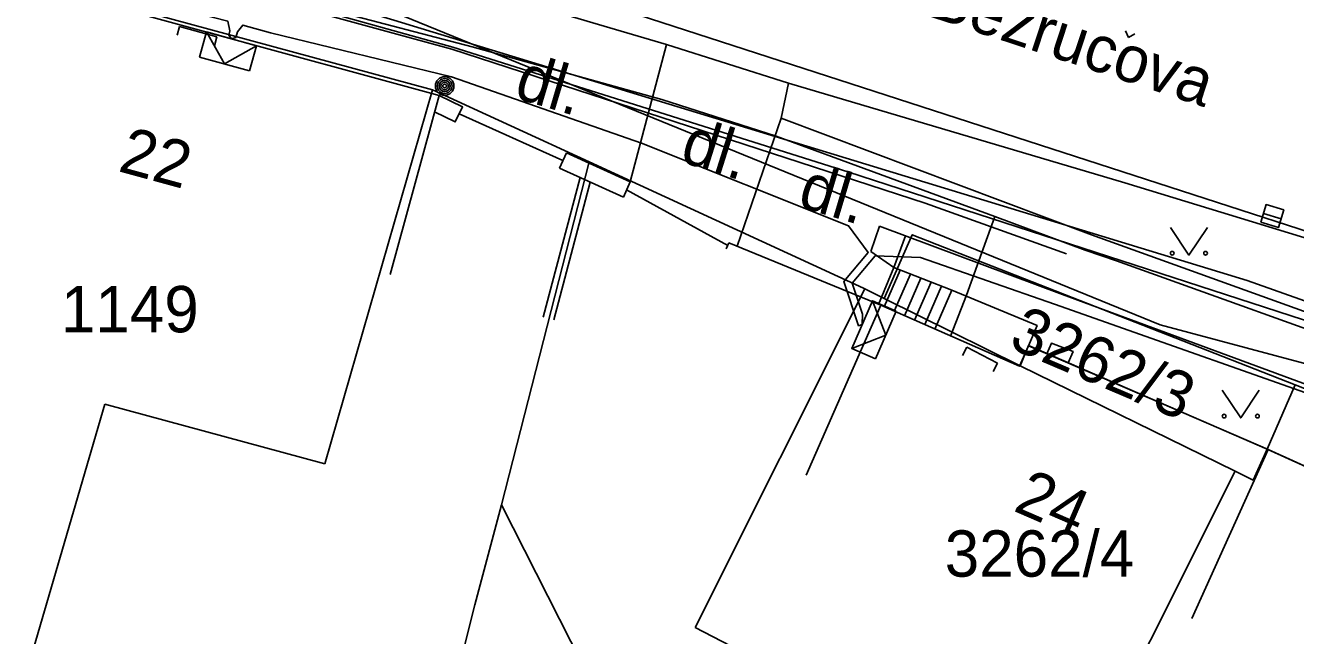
# Model space of a CAD drawing. Extents: x -601580 to 4, y -1204314 to 4.
# Drawn here: x -599783.34 to -599749.08, y -1203349.28 to -1203332.82 of the extents above; entities that cross this region are included whole.
import ezdxf

# ---------------------------------------------------------------- set-up
doc = ezdxf.new("R2010")
doc.units = 0
for name, color, linetype in [('00-EON NN', 7, 'Continuous'), ('00-INNOGY-NTL', 7, 'Continuous'), ('00-KN-HRANICE PARCEL', 7, 'Continuous'), ('00-KN-PARC. CISLA', 7, 'Continuous'), ('00-KN-VNITRNI KRESBA', 7, 'Continuous'), ('00-POLOHOPIS', 7, 'Continuous'), ('00-SITE KOM. KABEL', 7, 'Continuous'), ('00-VAK-VODA-RAD IGIS', 7, 'Continuous'), ('Vrstva 25', 7, 'Continuous'), ('Vrstva 26', 7, 'Continuous'), ('Vrstva 27', 7, 'Continuous'), ('Vrstva 36', 7, 'Continuous'), ('Vrstva 6', 7, 'Continuous'), ('Vrstva 9', 7, 'Continuous')]:
    doc.layers.add(name, color=color, linetype=linetype)

# ---------------------------------------------------------------- blocks, each defined once
blk = doc.blocks.new('6.01A_1266')
at = {"layer": 'Vrstva 25'}
for radius in [0.25, 0.2, 0.15, 0.1, 0.05]:
    blk.add_circle((0, 0), radius, dxfattribs=at)
blk = doc.blocks.new('6.30_324')
at = {"layer": 'Vrstva 27'}
blk.add_line((-0.25, 0), (0.25, 0), dxfattribs=at)
blk.add_lwpolyline([(-0.25, -0.25), (0.25, -0.25), (0.25, 0.25), (-0.25, 0.25)], close=True, dxfattribs=at)
blk = doc.blocks.new('3.14_144')
at = {"layer": 'Vrstva 36'}
blk.add_lwpolyline([(-0.5, 0.75), (0, 0), (0.5, 0.75)], dxfattribs=at)
for centre in [(-0.45, 0.05), (0.449, 0.05)]:
    blk.add_circle(centre, 0.05, dxfattribs=at)
blk = doc.blocks.new('3.14_154')
at = {"layer": 'Vrstva 36'}
blk.add_lwpolyline([(-0.5, 0.75), (0, 0), (0.5, 0.75)], dxfattribs=at)
for centre in [(-0.45, 0.05), (0.449, 0.05)]:
    blk.add_circle(centre, 0.05, dxfattribs=at)
blk = doc.blocks.new('VCHOD_252')
at = {"layer": 'Vrstva 6'}
blk.add_line((0, 0.25), (0, 0), dxfattribs=at)
blk = doc.blocks.new('VCHOD_254')
at = {"layer": 'Vrstva 6'}
blk.add_line((0, 0.25), (0, 0), dxfattribs=at)
blk = doc.blocks.new('VCHOD_256')
at = {"layer": 'Vrstva 6'}
blk.add_line((0, 0.25), (0, 0), dxfattribs=at)
blk = doc.blocks.new('VCHOD_258')
at = {"layer": 'Vrstva 6'}
blk.add_line((0, 0.25), (0, 0), dxfattribs=at)
blk = doc.blocks.new('NN630')
at = {"layer": 'Vrstva 9'}
for points in [[(-3, -700), (-703, 0)], [(-703, -700), (-703, 0), (697, 0), (697, -700)], [(-3, -700), (697, 0)], [(-703, -700), (697, -700)]]:
    blk.add_lwpolyline(points, dxfattribs=at)

msp = doc.modelspace()

# ---------------------------------------------------------------- linework, layer by layer
at = {"layer": '00-EON NN'}
for points in [[(-599786.53, -1203330.36), (-599782.77, -1203331.45), (-599777.88, -1203332.71), (-599777.827, -1203332.968), (-599777.86, -1203333.086), (-599777.783, -1203333.184), (-599777.669, -1203333.146), (-599777.626, -1203332.99), (-599777.48, -1203332.81), (-599776.73, -1203333.02), (-599771.85, -1203334.21), (-599766.72, -1203336), (-599761.14, -1203338.23), (-599760.611, -1203338.947), (-599761.262, -1203339.729), (-599760.866, -1203340.921), (-599760.771, -1203340.889)], [(-599760.771, -1203340.889), (-599760.759, -1203340.609), (-599761.038, -1203339.771), (-599760.423, -1203339.035), (-599759.2, -1203339.08), (-599755.58, -1203340.34), (-599747.12, -1203343.33), (-599742.31, -1203345.18), (-599739.75, -1203346.25), (-599739.539, -1203346.483), (-599739.944, -1203347.797), (-599740.403, -1203348.953), (-599740.344, -1203349.075), (-599740.222, -1203349.039), (-599739.756, -1203347.863), (-599739.289, -1203346.359), (-599739.12, -1203346.15), (-599735.04, -1203347.7), (-599731.04, -1203349.25), (-599729.807, -1203349.645)]]:
    msp.add_lwpolyline(points, dxfattribs=at)
at = {"layer": '00-INNOGY-NTL'}
msp.add_lwpolyline([(-599755.262, -1203338.986), (-599759.07, -1203337.62), (-599771.84, -1203333.46), (-599779.26, -1203331.43), (-599784.38, -1203330.03), (-599784.72, -1203329.94), (-599809.28, -1203323.19), (-599809.78, -1203323.05), (-599823.19, -1203319.4)], dxfattribs=at)
at = {"layer": '00-KN-HRANICE PARCEL'}
for p, q in [((-599770.5, -1203345.75), (-599768.14, -1203336.5)), ((-599760.74, -1203339.91), (-599768.14, -1203336.5)), ((-599756.51, -1203342), (-599760.18, -1203340.19)), ((-599750.71, -1203344.85), (-599756.51, -1203342)), ((-599749.85, -1203344.25), (-599749.09, -1203342.52)), ((-599749.09, -1203342.52), (-599731.4, -1203349.49)), ((-599771.22, -1203348.45), (-599770.5, -1203345.75)), ((-599762.11, -1203362.29), (-599770.5, -1203345.75)), ((-599773.46, -1203357.4), (-599771.22, -1203348.45))]:
    msp.add_line(p, q, dxfattribs=at)
for points in [[(-599921.72, -1203290.33), (-599917.89, -1203290.73), (-599893.03, -1203296.87), (-599826.78, -1203316.44), (-599809.21, -1203321.87), (-599773.41, -1203332.68), (-599750.39, -1203339.7), (-599709.77, -1203354.1), (-599677.07, -1203366.64), (-599676.9, -1203368.84), (-599676.98, -1203369.55)], [(-599768.14, -1203336.5), (-599772.36, -1203334.56), (-599784.87, -1203331.16)], [(-599760.18, -1203340.19), (-599759.42, -1203338.47), (-599749.09, -1203342.52)], [(-599760.18, -1203340.19), (-599760.7, -1203339.93), (-599760.74, -1203339.91)], [(-599756.51, -1203342), (-599756.28, -1203341.46), (-599749.85, -1203344.25)], [(-599749.85, -1203344.25), (-599750.22, -1203345.09), (-599750.71, -1203344.85)], [(-599740.06, -1203349.19), (-599743.74, -1203347.58), (-599743.53, -1203347.11), (-599749.85, -1203344.25)], [(-599750.71, -1203344.85), (-599755.29, -1203353.98), (-599755.39, -1203354.18), (-599759.18, -1203361.73)]]:
    msp.add_lwpolyline(points, dxfattribs=at)
at = {"layer": '00-KN-VNITRNI KRESBA'}
for p, q in [((-599772.36, -1203334.56), (-599775.27, -1203344.65)), ((-599765.28, -1203349.06), (-599760.7, -1203339.93)), ((-599781.2, -1203343.04), (-599783.98, -1203352.56)), ((-599775.27, -1203344.65), (-599781.2, -1203343.04)), ((-599755.39, -1203354.18), (-599765.28, -1203349.06))]:
    msp.add_line(p, q, dxfattribs=at)
at = {"layer": '00-POLOHOPIS'}
for p, q in [((-599771.919, -1203331.604), (-599766.046, -1203333.336)), ((-599778.178, -1203333.13), (-599779.184, -1203332.846)), ((-599766.046, -1203333.336), (-599767.027, -1203337.043)), ((-599766.046, -1203333.336), (-599762.755, -1203334.376)), ((-599762.953, -1203335.326), (-599762.755, -1203334.376)), ((-599762.755, -1203334.376), (-599753.685, -1203337.067)), ((-599768.844, -1203336.468), (-599771.646, -1203335.21)), ((-599762.953, -1203335.326), (-599764.14, -1203338.778)), ((-599754.589, -1203338.472), (-599762.953, -1203335.326)), ((-599768.75, -1203336.261), (-599768.936, -1203336.671)), ((-599767.027, -1203337.043), (-599768.75, -1203336.261)), ((-599768.936, -1203336.671), (-599767.213, -1203337.453)), ((-599768.382, -1203336.922), (-599769.375, -1203340.69)), ((-599768.105, -1203337.048), (-599769.085, -1203340.767)), ((-599767.213, -1203337.453), (-599767.027, -1203337.043)), ((-599753.685, -1203337.067), (-599747.822, -1203338.86)), ((-599764.398, -1203338.759), (-599767.126, -1203337.26)), ((-599760.536, -1203338.924), (-599760.304, -1203338.237)), ((-599760.304, -1203338.237), (-599755.364, -1203340.081)), ((-599759.603, -1203338.499), (-599759.921, -1203339.351)), ((-599748.418, -1203340.694), (-599754.589, -1203338.472)), ((-599764.367, -1203338.684), (-599764.436, -1203338.85)), ((-599764.367, -1203338.684), (-599760.271, -1203340.371)), ((-599759.921, -1203339.351), (-599760.536, -1203338.924)), ((-599760.182, -1203340.41), (-599759.748, -1203339.419)), ((-599759.907, -1203340.53), (-599759.468, -1203339.529)), ((-599759.632, -1203340.651), (-599759.188, -1203339.638)), ((-599759.357, -1203340.771), (-599758.909, -1203339.748)), ((-599759.083, -1203340.892), (-599758.629, -1203339.857)), ((-599758.808, -1203341.012), (-599758.35, -1203339.967)), ((-599755.364, -1203340.081), (-599742.153, -1203344.961)), ((-599757.952, -1203341.502), (-599757.124, -1203341.931))]:
    msp.add_line(p, q, dxfattribs=at)
for points in [[(-599773.501, -1203339.536), (-599772.184, -1203334.712), (-599784.724, -1203331.289), (-599786.041, -1203336.112)], [(-599753.668, -1203332.964), (-599753.59, -1203333.148)], [(-599753.416, -1203333.049), (-599753.59, -1203333.148)], [(-599772.184, -1203334.712), (-599771.553, -1203335.02), (-599771.75, -1203335.424), (-599772.305, -1203335.154)], [(-599756.284, -1203341.463), (-599756.052, -1203340.919), (-599758.35, -1203339.967), (-599759.921, -1203339.351), (-599760.331, -1203340.346)], [(-599751.882, -1203348.82), (-599749.819, -1203344.265), (-599756.284, -1203341.463), (-599756.523, -1203342.014), (-599760.271, -1203340.371), (-599762.278, -1203344.951)], [(-599755.215, -1203341.926), (-599755.082, -1203341.619), (-599755.665, -1203341.393), (-599755.788, -1203341.678)], [(-599742.03, -1203353.8), (-599739.968, -1203349.245), (-599743.729, -1203347.542), (-599743.534, -1203347.111), (-599749.819, -1203344.265), (-599751.882, -1203348.82)]]:
    msp.add_lwpolyline(points, dxfattribs=at)
at = {"layer": '00-SITE KOM. KABEL'}
for points in [[(-599790.07, -1203328.52), (-599779.22, -1203331.34), (-599771.81, -1203333.41), (-599761.16, -1203336.77), (-599748.51, -1203340.88), (-599738.08, -1203344.54)], [(-599757.19, -1203337.98), (-599763.09, -1203335.81), (-599766.18, -1203334.82), (-599771.29, -1203333.4), (-599778.72, -1203331.45)], [(-599771.29, -1203333.4), (-599766.18, -1203334.82), (-599763.09, -1203335.81)], [(-599758.39, -1203341.2), (-599757.96, -1203340.1), (-599757.62, -1203339.17), (-599757.19, -1203337.98)], [(-599757.19, -1203337.98), (-599754.76, -1203338.88), (-599753.91, -1203339.17), (-599746.35, -1203341.89), (-599738.57, -1203344.75)], [(-599754.76, -1203338.88), (-599753.91, -1203339.17)], [(-599757.62, -1203339.17), (-599757.96, -1203340.1)]]:
    msp.add_lwpolyline(points, dxfattribs=at)
at = {"layer": '00-VAK-VODA-RAD IGIS'}
for points in [[(-599720.355, -1203347.776), (-599729.23, -1203344.714), (-599770.31, -1203331.391), (-599796.664, -1203323.541), (-599826.579, -1203315.23), (-599851.958, -1203307.785), (-599870.565, -1203302.595), (-599896.257, -1203294.737), (-599907.177, -1203291.811)], [(-599902.046, -1203295.125), (-599868.378, -1203304.731), (-599831.703, -1203315.287), (-599809.417, -1203321.634), (-599778.543, -1203330.362), (-599752.729, -1203340.898), (-599712.522, -1203351.656), (-599694.336, -1203358.224), (-599621.861, -1203382.557), (-599578.525, -1203396.236), (-599556.78, -1203403.208)]]:
    msp.add_lwpolyline(points, dxfattribs=at)

# ---------------------------------------------------------------- block references
at = {"layer": '00-POLOHOPIS'}
for name, p, xscale, yscale, rotation in [('VCHOD_258', (-599779.184, -1203332.846), 0.99999791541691, 0.9999979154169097, 164.23535491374), ('VCHOD_256', (-599778.178, -1203333.13), 0.99999791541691, 0.9999979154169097, 164.23535491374), ('6.01A_1266', (-599772.034, -1203334.455), 0.9999980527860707, 0.9999980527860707, 79.99987164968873), ('6.30_324', (-599749.709, -1203337.964), 1.00000127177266, 1.00000127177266, -17.004375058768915), ('VCHOD_254', (-599757.952, -1203341.502), 1.0000012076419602, 1.0000012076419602, 152.61054849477), ('VCHOD_252', (-599757.124, -1203341.931), 1.0000012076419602, 1.0000012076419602, 152.61054849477)]:
    msp.add_blockref(name, p, dxfattribs=dict(at, xscale=xscale, yscale=yscale, rotation=rotation))
for name, p in [('3.14_144', (-599751.957, -1203339.018)), ('3.14_154', (-599750.559, -1203343.41))]:
    msp.add_blockref(name, p, dxfattribs=at)
at = {"layer": 'Vrstva 26', "xscale": 0.001, "yscale": 0.0010000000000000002}
for p, rotation in [((-599777.783, -1203333.184), -15.36161393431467), ((-599760.771, -1203340.889), 66.3505639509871)]:
    msp.add_blockref('NN630', p, dxfattribs=dict(at, rotation=rotation))

# ---------------------------------------------------------------- texts
at = {"layer": '00-KN-PARC. CISLA'}
for s, p in [('1149', (-599782.387, -1203341.1)), ('3262/4', (-599758.544, -1203347.693))]:
    msp.add_text(s, height=1.25, dxfattribs=at).set_placement(p)
msp.add_text('3262/3', height=1.25, rotation=337, dxfattribs=at).set_placement((-599756.858, -1203341.497))
at = {"layer": '00-POLOHOPIS'}
for s, rotation, p in [('Bezrucova', 341.7395, (-599759.039, -1203332.553)), ('dl.', 343.3557, (-599770.199, -1203334.763)), ('dl.', 342.4628, (-599765.726, -1203336.479)), ('22', 344.7321, (-599780.876, -1203336.745)), ('dl.', 343.3557, (-599762.55, -1203337.697)), ('24', 336.5676, (-599756.728, -1203345.902))]:
    msp.add_text(s, height=1.25, rotation=rotation, dxfattribs=at).set_placement(p)

doc.saveas('drawing.dxf')
